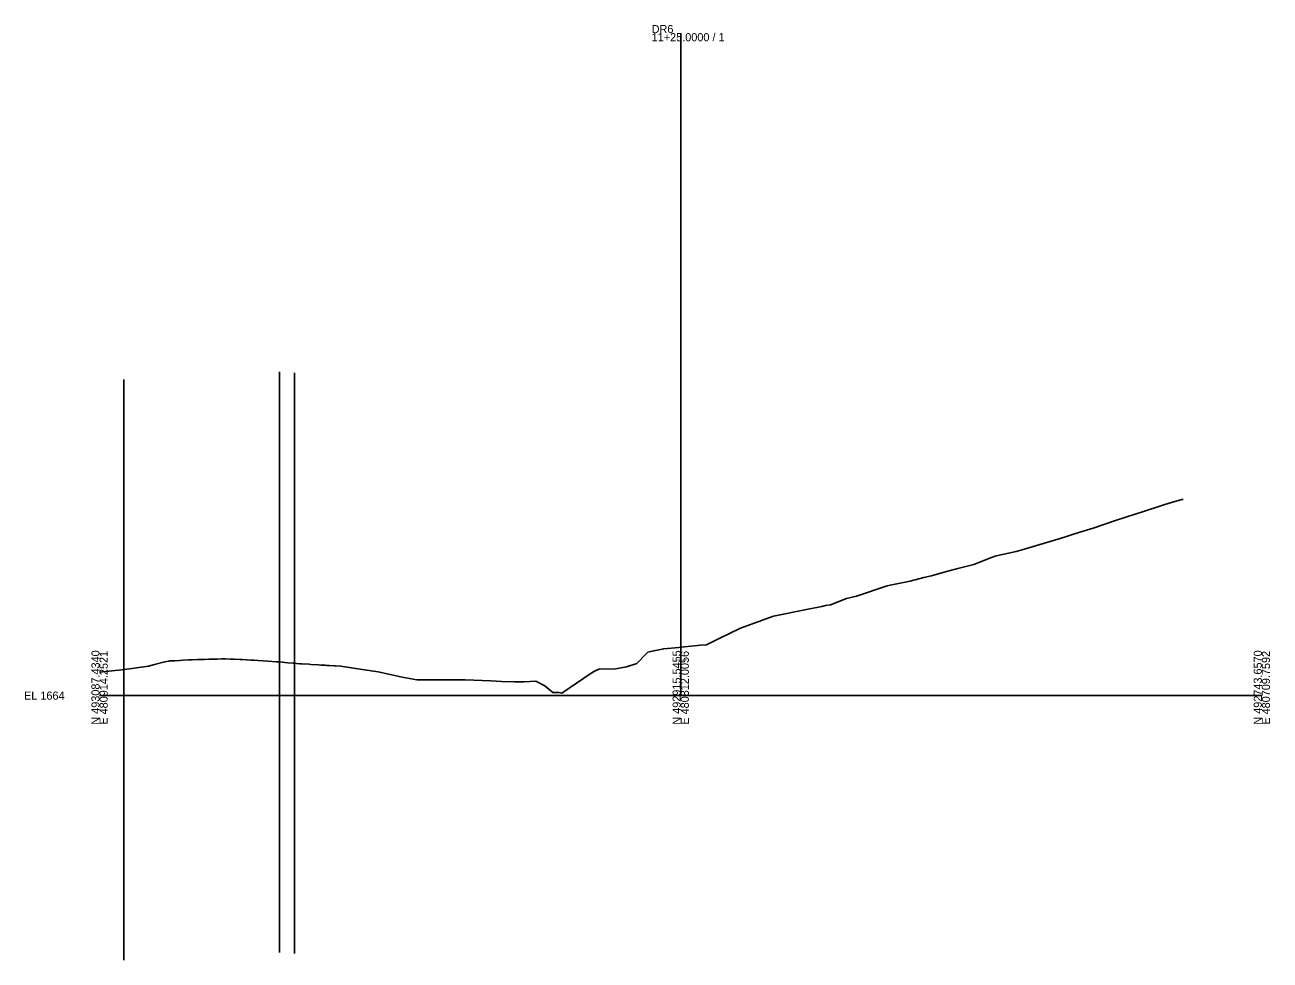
# Model space of a CAD drawing. Extents: x -26 to 403, y -88 to 5647.
# Drawn here: x -25.7 to 402.8, y 2408.9 to 2731 of the extents above; entities that cross this region are included whole.
import ezdxf

# ---------------------------------------------------------------- set-up
doc = ezdxf.new("R2010")
doc.units = 0
for name, color, linetype in [('Exist Cross Section Cell', 7, 'Continuous'), ('Exist XS Center Line Elevation Label', 7, 'Continuous'), ('Exist XS Ground Line', 7, 'Continuous'), ('Scratch_Level_7', 7, 'Continuous')]:
    doc.layers.add(name, color=color, linetype=linetype)

msp = doc.modelspace()

# ---------------------------------------------------------------- linework, layer by layer
at = {"layer": 'Exist Cross Section Cell'}
for p, q in [((200, 2500), (200, 2728.15)), ((0, 2500), (200, 2500)), ((200, 2500), (400, 2500))]:
    msp.add_line(p, q, dxfattribs=at)
at = {"layer": 'Exist XS Ground Line'}
msp.add_lwpolyline([(0, 2508.06), (4.2, 2508.56), (7.78, 2508.84), (16.83, 2510.19), (18.86, 2510.68), (22.52, 2511.6), (23.79, 2511.92), (24.17, 2511.94), (26.02, 2512.04), (27.58, 2512.13), (28.74, 2512.18), (30.65, 2512.28), (31.72, 2512.34), (33.7, 2512.43), (34.3, 2512.46), (34.63, 2512.46), (36.16, 2512.49), (37.58, 2512.52), (37.9, 2512.52), (38.43, 2512.54), (39.72, 2512.58), (40.45, 2512.6), (42.03, 2512.62), (43.38, 2512.62), (45.21, 2512.61), (46.3, 2512.56), (48.26, 2512.46), (49.21, 2512.4), (50.55, 2512.32), (52.08, 2512.23), (53.15, 2512.17), (54.64, 2512.08), (57.94, 2511.87), (60.8, 2511.66), (61.55, 2511.6), (62.82, 2511.49), (63.81, 2511.42), (64.79, 2511.34), (66.63, 2511.19), (67.05, 2511.16), (67.79, 2511.1), (68.93, 2511.01), (69.58, 2510.96), (72.12, 2510.8), (72.71, 2510.76), (75.38, 2510.59), (76.24, 2510.54), (77.62, 2510.47), (78.27, 2510.43), (79.02, 2510.39), (80.75, 2510.29), (81.24, 2510.27), (83.07, 2510.15), (90.35, 2509.01), (95.9, 2508.17), (104.15, 2506.38), (109.17, 2505.49), (119.42, 2505.48), (125.77, 2505.43), (134.68, 2505.13), (138.33, 2504.92), (142.83, 2504.77), (146.13, 2504.7), (150.19, 2504.94), (153.25, 2503.42), (155.94, 2501.11), (156.52, 2501.08), (158.17, 2501.03), (158.67, 2500.92), (159.1, 2500.84), (169.17, 2507.7), (171, 2508.75), (171.94, 2509.13), (172.84, 2509.23), (176.94, 2509.07), (181.38, 2509.88), (184.95, 2511.1), (188.13, 2514.43), (188.74, 2515.01), (190.18, 2515.35), (194.14, 2516.17), (199.33, 2516.59), (200, 2516.66), (204.72, 2517.2), (206.86, 2517.39), (208.83, 2517.54), (213.06, 2519.59), (220.63, 2523.26), (227.76, 2525.88), (231.88, 2527.36), (243.82, 2529.81), (248.55, 2530.72), (249.82, 2531.1), (251.51, 2531.33), (257.11, 2533.42), (260.45, 2534.29), (271.07, 2537.82), (272.09, 2538.08), (279.01, 2539.44), (283.73, 2540.69), (286.3, 2541.25), (290.64, 2542.52), (295.36, 2543.81), (300.9, 2545.17), (307, 2547.61), (308.19, 2547.99), (310.2, 2548.54), (315.49, 2549.67), (318.64, 2550.56), (329.76, 2553.87), (330.28, 2554.03), (337.38, 2556.28), (341.91, 2557.7), (349.33, 2560.15), (353.55, 2561.59), (359.27, 2563.42), (365.19, 2565.34), (366.57, 2565.8), (368.89, 2566.49), (372.52, 2567.6), (372.88, 2567.55)], dxfattribs=at)
at = {"layer": 'Scratch_Level_7'}
for p, q in [((61.94, 2611.57), (61.94, 2411.57)), ((67.06, 2611.16), (67.06, 2411.16)), ((8.33, 2608.92), (8.33, 2408.92))]:
    msp.add_line(p, q, dxfattribs=at)

# ---------------------------------------------------------------- texts
at = {"layer": 'Exist Cross Section Cell'}
for s, p in [('DR6', (190, 2728.15)), ('11+25.0000 / 1', (190, 2725.35)), ('EL 1664', (-26, 2498.6))]:
    msp.add_text(s, height=2.8, dxfattribs=at).set_placement(p)
for s, p in [('N 493087.4340', (0, 2490)), ('E 480914.2521', (2.8, 2490)), ('N 492915.5455', (200, 2490)), ('E 480812.0056', (202.8, 2490)), ('N 492743.6570', (400, 2490)), ('E 480709.7592', (402.8, 2490))]:
    msp.add_text(s, height=2.8, rotation=90, dxfattribs=at).set_placement(p)
at = {"layer": 'Exist XS Center Line Elevation Label'}
msp.add_text('1680.66', height=0.75, dxfattribs=at).set_placement((198.27, 2511.91))

doc.saveas('drawing.dxf')
